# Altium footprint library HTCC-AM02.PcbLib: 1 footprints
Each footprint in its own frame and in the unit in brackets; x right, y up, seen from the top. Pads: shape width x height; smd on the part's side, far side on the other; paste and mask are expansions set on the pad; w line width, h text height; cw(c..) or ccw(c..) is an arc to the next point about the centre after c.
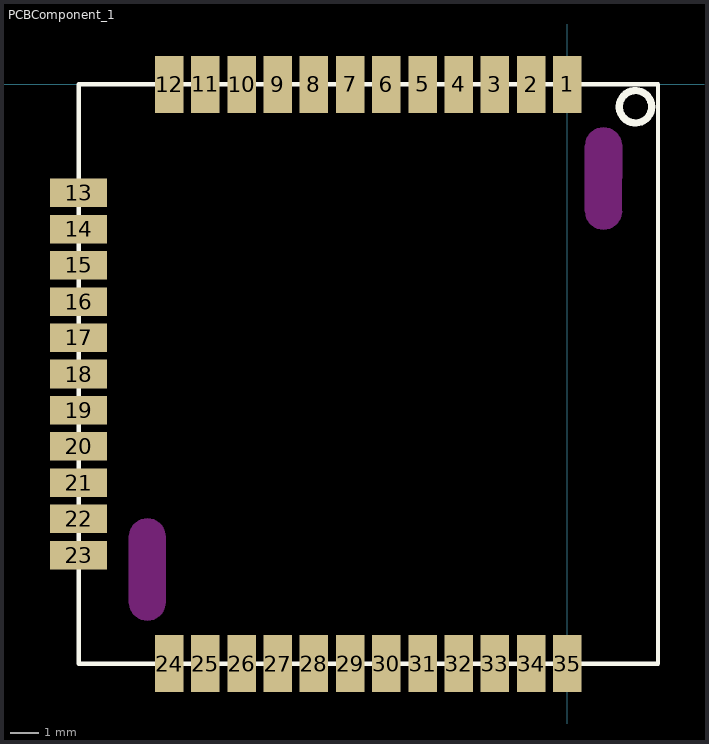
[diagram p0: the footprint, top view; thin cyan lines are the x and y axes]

## PCBComponent_1 [mm]
pads (35):
  rect 1x2 smd: 1(0,0) 2(-1.27,0) 3(-2.54,0) 4(-3.81,0) 5(-5.08,0) 6(-6.35,0) 7(-7.62,0) 8(-8.89,0) 9(-10.16,0) 10(-11.43,0) 11(-12.7,0) 12(-13.97,0) 24(-13.97,-20.32) 25(-12.7,-20.32) 26(-11.43,-20.32) 27(-10.16,-20.32) 28(-8.89,-20.32) 29(-7.62,-20.32) 30(-6.35,-20.32) 31(-5.08,-20.32) 32(-3.81,-20.32) 33(-2.54,-20.32) 34(-1.27,-20.32) 35(0,-20.32)
  rect 2x1 smd: 13(-17.145,-3.81) 14(-17.145,-5.08) 15(-17.145,-6.35) 16(-17.145,-7.62) 17(-17.145,-8.89) 18(-17.145,-10.16) 19(-17.145,-11.43) 20(-17.145,-12.7) 21(-17.145,-13.97) 22(-17.145,-15.24) 23(-17.145,-16.51)
Top Overlay:
  circle w0.254: c2.388,-0.787 r0.568
  lines w0.152: 0.635,0 0.686,0 ; -17.145,-20.32 3.175,-20.32 3.175,0 -17.145,0 -17.145,-20.32
Keep-Out Layer:
  region: -15.381,-18.161 -15.332,-18.408 -15.192,-18.619 -14.981,-18.759 -14.733,-18.808 -14.732,-18.808 -14.731,-18.808 -14.483,-18.759 -14.272,-18.619 -14.132,-18.408 -14.083,-18.161 -14.095,-18.161 -14.083,-15.875 -14.132,-15.628 -14.272,-15.417 -14.483,-15.277 -14.731,-15.228 -14.732,-15.228 -14.733,-15.228 -14.981,-15.277 -15.192,-15.417 -15.332,-15.628 -15.381,-15.875 -15.369,-15.875
  region: 0.619,-4.445 0.668,-4.692 0.808,-4.903 1.019,-5.043 1.267,-5.092 1.268,-5.092 1.269,-5.092 1.517,-5.043 1.728,-4.903 1.868,-4.692 1.917,-4.445 1.905,-4.445 1.917,-2.159 1.868,-1.912 1.728,-1.701 1.517,-1.561 1.269,-1.512 1.268,-1.512 1.267,-1.512 1.019,-1.561 0.808,-1.701 0.668,-1.912 0.619,-2.159 0.631,-2.159
  lines w0.025: -15.369,-18.161 ccw(c-14.733,-18.16) -14.732,-18.796 ccw(c-14.731,-18.16) -14.095,-18.161 -14.095,-15.875 ccw(c-14.731,-15.876) -14.732,-15.24 ccw(c-14.733,-15.876) -15.369,-15.875 -15.369,-18.161 ; 0.631,-4.445 ccw(c1.267,-4.444) 1.268,-5.08 ccw(c1.269,-4.444) 1.905,-4.445 1.905,-2.159 ccw(c1.269,-2.16) 1.268,-1.524 ccw(c1.267,-2.16) 0.631,-2.159 0.631,-4.445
